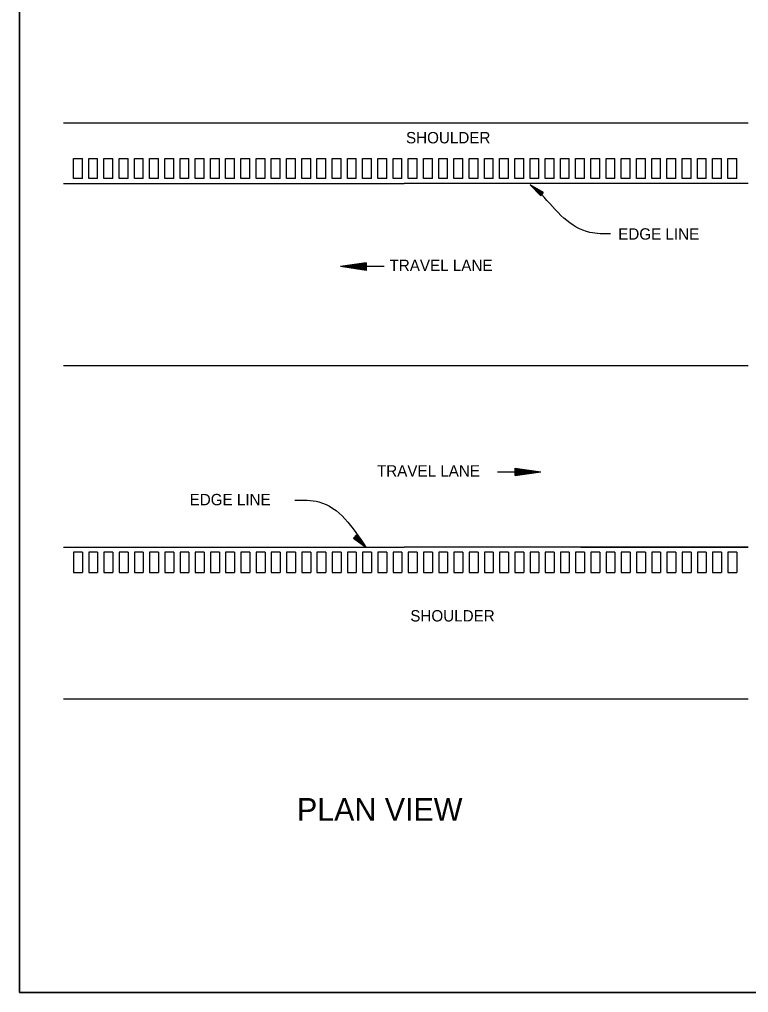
# Model space of a CAD drawing. Extents: x 8229 to 8749, y 14916 to 18021.
# Drawn here: x 8230.8 to 8356.5, y 15353.5 to 15521.2 of the extents above; entities that cross this region are included whole.
import ezdxf

# ---------------------------------------------------------------- set-up
doc = ezdxf.new("R2010")
doc.units = 0
doc.layers.add('Default', color=7, linetype='Continuous')
doc.layers.add('DSN_DRFT_Junk-No-Plot', color=7, linetype='Continuous')

msp = doc.modelspace()

# ---------------------------------------------------------------- linework, layer by layer
at = {"layer": 'Default'}
for p, q in [((8238.44, 15503.35), (8356.39, 15503.35)), ((8240.14, 15493.77), (8240.14, 15497.24)), ((8240.14, 15497.24), (8241.68, 15497.24)), ((8241.68, 15493.77), (8241.68, 15497.24)), ((8242.77, 15493.77), (8242.77, 15497.24)), ((8242.77, 15497.24), (8244.3, 15497.24)), ((8244.3, 15493.77), (8244.3, 15497.24)), ((8245.39, 15493.77), (8245.39, 15497.24)), ((8245.39, 15497.24), (8246.92, 15497.24)), ((8246.92, 15493.77), (8246.92, 15497.24)), ((8248.01, 15493.77), (8248.01, 15497.24)), ((8248.01, 15497.24), (8249.54, 15497.24)), ((8249.54, 15493.77), (8249.54, 15497.24)), ((8250.63, 15493.77), (8250.63, 15497.24)), ((8250.63, 15497.24), (8252.17, 15497.24)), ((8252.17, 15493.77), (8252.17, 15497.24)), ((8253.25, 15493.77), (8253.25, 15497.24)), ((8253.25, 15497.24), (8254.79, 15497.24)), ((8254.79, 15493.77), (8254.79, 15497.24)), ((8255.88, 15493.77), (8255.88, 15497.24)), ((8255.88, 15497.24), (8257.41, 15497.24)), ((8257.41, 15493.77), (8257.41, 15497.24)), ((8258.5, 15493.77), (8258.5, 15497.24)), ((8258.5, 15497.24), (8260.03, 15497.24)), ((8260.03, 15493.77), (8260.03, 15497.24)), ((8261.12, 15493.77), (8261.12, 15497.24)), ((8261.12, 15497.24), (8262.65, 15497.24)), ((8262.65, 15493.77), (8262.65, 15497.24)), ((8263.74, 15493.77), (8263.74, 15497.24)), ((8263.74, 15497.24), (8265.28, 15497.24)), ((8265.28, 15493.77), (8265.28, 15497.24)), ((8266.36, 15493.77), (8266.36, 15497.24)), ((8266.36, 15497.24), (8267.9, 15497.24)), ((8267.9, 15493.77), (8267.9, 15497.24)), ((8268.99, 15493.77), (8268.99, 15497.24)), ((8268.99, 15497.24), (8270.52, 15497.24)), ((8270.52, 15493.77), (8270.52, 15497.24)), ((8271.61, 15493.77), (8271.61, 15497.24)), ((8271.61, 15497.24), (8273.14, 15497.24)), ((8273.14, 15493.77), (8273.14, 15497.24)), ((8274.23, 15493.77), (8274.23, 15497.24)), ((8274.23, 15497.24), (8275.76, 15497.24)), ((8275.76, 15493.77), (8275.76, 15497.24)), ((8276.85, 15493.77), (8276.85, 15497.24)), ((8276.85, 15497.24), (8278.39, 15497.24)), ((8278.39, 15493.77), (8278.39, 15497.24)), ((8279.47, 15493.77), (8279.47, 15497.24)), ((8279.47, 15493.77), (8279.47, 15497.24)), ((8279.47, 15497.24), (8281.01, 15497.24)), ((8281.01, 15493.77), (8281.01, 15497.24)), ((8282.1, 15493.77), (8282.1, 15497.24)), ((8282.1, 15497.24), (8283.63, 15497.24)), ((8283.63, 15493.77), (8283.63, 15497.24)), ((8284.72, 15493.77), (8284.72, 15497.24)), ((8284.72, 15497.24), (8286.25, 15497.24)), ((8286.25, 15493.77), (8286.25, 15497.24)), ((8287.34, 15493.77), (8287.34, 15497.24)), ((8287.34, 15497.24), (8288.87, 15497.24)), ((8288.87, 15493.77), (8288.87, 15497.24)), ((8289.96, 15493.77), (8289.96, 15497.24)), ((8289.96, 15497.24), (8291.5, 15497.24)), ((8291.5, 15493.77), (8291.5, 15497.24)), ((8292.59, 15493.77), (8292.59, 15497.24)), ((8292.59, 15497.24), (8294.12, 15497.24)), ((8294.12, 15493.77), (8294.12, 15497.24)), ((8295.21, 15493.77), (8295.21, 15497.24)), ((8295.21, 15497.24), (8296.74, 15497.24)), ((8296.74, 15493.77), (8296.74, 15497.24)), ((8297.83, 15493.77), (8297.83, 15497.24)), ((8297.83, 15497.24), (8299.36, 15497.24)), ((8299.36, 15493.77), (8299.36, 15497.24)), ((8300.45, 15493.77), (8300.45, 15497.24)), ((8300.45, 15497.24), (8301.99, 15497.24)), ((8301.99, 15493.77), (8301.99, 15497.24)), ((8303.07, 15493.77), (8303.07, 15497.24)), ((8303.07, 15497.24), (8304.61, 15497.24)), ((8304.61, 15493.77), (8304.61, 15497.24)), ((8305.7, 15493.77), (8305.7, 15497.24)), ((8305.7, 15497.24), (8307.23, 15497.24)), ((8307.23, 15493.77), (8307.23, 15497.24)), ((8308.32, 15493.77), (8308.32, 15497.24)), ((8308.32, 15497.24), (8309.85, 15497.24)), ((8309.85, 15493.77), (8309.85, 15497.24)), ((8310.94, 15493.77), (8310.94, 15497.24)), ((8310.94, 15497.24), (8312.47, 15497.24)), ((8312.47, 15493.77), (8312.47, 15497.24)), ((8313.56, 15493.77), (8313.56, 15497.24)), ((8313.56, 15497.24), (8315.1, 15497.24)), ((8315.1, 15493.77), (8315.1, 15497.24)), ((8316.18, 15493.77), (8316.18, 15497.24)), ((8316.18, 15497.24), (8317.72, 15497.24)), ((8317.72, 15493.77), (8317.72, 15497.24)), ((8318.81, 15493.77), (8318.81, 15497.24)), ((8318.81, 15497.24), (8320.34, 15497.24)), ((8320.34, 15493.77), (8320.34, 15497.24)), ((8321.43, 15493.77), (8321.43, 15497.24)), ((8321.43, 15497.24), (8322.96, 15497.24)), ((8322.96, 15493.77), (8322.96, 15497.24)), ((8324.05, 15493.77), (8324.05, 15497.24)), ((8324.05, 15497.24), (8325.58, 15497.24)), ((8325.58, 15493.77), (8325.58, 15497.24)), ((8326.67, 15493.77), (8326.67, 15497.24)), ((8326.67, 15497.24), (8328.21, 15497.24)), ((8328.21, 15493.77), (8328.21, 15497.24)), ((8329.29, 15493.77), (8329.29, 15497.24)), ((8329.29, 15497.24), (8330.83, 15497.24)), ((8330.83, 15493.77), (8330.83, 15497.24)), ((8331.92, 15493.77), (8331.92, 15497.24)), ((8331.92, 15497.24), (8333.45, 15497.24)), ((8333.45, 15493.77), (8333.45, 15497.24)), ((8334.54, 15493.77), (8334.54, 15497.24)), ((8334.54, 15497.24), (8336.07, 15497.24)), ((8336.07, 15493.77), (8336.07, 15497.24)), ((8337.16, 15493.77), (8337.16, 15497.24)), ((8337.16, 15497.24), (8338.69, 15497.24)), ((8338.69, 15493.77), (8338.69, 15497.24)), ((8339.78, 15493.77), (8339.78, 15497.24)), ((8339.78, 15497.24), (8341.32, 15497.24)), ((8341.32, 15493.77), (8341.32, 15497.24)), ((8342.41, 15493.77), (8342.41, 15497.24)), ((8342.41, 15497.24), (8343.94, 15497.24)), ((8343.94, 15493.77), (8343.94, 15497.24)), ((8345.03, 15493.77), (8345.03, 15497.24)), ((8345.03, 15497.24), (8346.56, 15497.24)), ((8346.56, 15493.77), (8346.56, 15497.24)), ((8347.65, 15493.77), (8347.65, 15497.24)), ((8347.65, 15497.24), (8349.18, 15497.24)), ((8349.18, 15493.77), (8349.18, 15497.24)), ((8350.27, 15493.77), (8350.27, 15497.24)), ((8350.27, 15497.24), (8351.81, 15497.24)), ((8351.81, 15493.77), (8351.81, 15497.24)), ((8352.89, 15493.77), (8352.89, 15497.24)), ((8352.89, 15497.24), (8354.43, 15497.24)), ((8354.43, 15493.77), (8354.43, 15497.24)), ((8241.68, 15493.77), (8240.14, 15493.77)), ((8244.3, 15493.77), (8242.77, 15493.77)), ((8246.92, 15493.77), (8245.39, 15493.77)), ((8249.54, 15493.77), (8248.01, 15493.77)), ((8252.17, 15493.77), (8250.63, 15493.77)), ((8254.79, 15493.77), (8253.25, 15493.77)), ((8257.41, 15493.77), (8255.88, 15493.77)), ((8260.03, 15493.77), (8258.5, 15493.77)), ((8262.65, 15493.77), (8261.12, 15493.77)), ((8265.28, 15493.77), (8263.74, 15493.77)), ((8267.9, 15493.77), (8266.36, 15493.77)), ((8270.52, 15493.77), (8268.99, 15493.77)), ((8273.14, 15493.77), (8271.61, 15493.77)), ((8275.76, 15493.77), (8274.23, 15493.77)), ((8278.39, 15493.77), (8276.85, 15493.77)), ((8281.01, 15493.77), (8279.47, 15493.77)), ((8283.63, 15493.77), (8282.1, 15493.77)), ((8286.25, 15493.77), (8284.72, 15493.77)), ((8288.87, 15493.77), (8287.34, 15493.77)), ((8291.5, 15493.77), (8289.96, 15493.77)), ((8294.12, 15493.77), (8292.59, 15493.77)), ((8296.74, 15493.77), (8295.21, 15493.77)), ((8299.36, 15493.77), (8297.83, 15493.77)), ((8301.99, 15493.77), (8300.45, 15493.77)), ((8304.61, 15493.77), (8303.07, 15493.77)), ((8307.23, 15493.77), (8305.7, 15493.77)), ((8309.85, 15493.77), (8308.32, 15493.77)), ((8312.47, 15493.77), (8310.94, 15493.77)), ((8315.1, 15493.77), (8313.56, 15493.77)), ((8317.72, 15493.77), (8316.18, 15493.77)), ((8320.34, 15493.77), (8318.81, 15493.77)), ((8322.96, 15493.77), (8321.43, 15493.77)), ((8325.58, 15493.77), (8324.05, 15493.77)), ((8328.21, 15493.77), (8326.67, 15493.77)), ((8330.83, 15493.77), (8329.29, 15493.77)), ((8333.45, 15493.77), (8331.92, 15493.77)), ((8336.07, 15493.77), (8334.54, 15493.77)), ((8338.69, 15493.77), (8337.16, 15493.77)), ((8341.32, 15493.77), (8339.78, 15493.77)), ((8343.94, 15493.77), (8342.41, 15493.77)), ((8346.56, 15493.77), (8345.03, 15493.77)), ((8349.18, 15493.77), (8347.65, 15493.77)), ((8351.81, 15493.77), (8350.27, 15493.77)), ((8354.43, 15493.77), (8352.89, 15493.77)), ((8238.44, 15492.9), (8297.14, 15492.9)), ((8356.39, 15492.9), (8297.14, 15492.9)), ((8320.65, 15490.76), (8318.85, 15492.7)), ((8321.14, 15491.38), (8318.85, 15492.7)), ((8320.69, 15490.81), (8319.19, 15492.43)), ((8321.1, 15491.32), (8319.19, 15492.43)), ((8321.05, 15491.27), (8319.54, 15492.15)), ((8320.73, 15490.87), (8319.54, 15492.15)), ((8320.77, 15490.92), (8319.88, 15491.88)), ((8321.02, 15491.22), (8319.88, 15491.88)), ((8320.97, 15491.17), (8320.23, 15491.6)), ((8320.81, 15490.97), (8320.23, 15491.6)), ((8320.93, 15491.11), (8320.57, 15491.33)), ((8320.85, 15491.02), (8320.57, 15491.33)), ((8320.65, 15490.76), (8321.14, 15491.38)), ((8290.56, 15479.24), (8286.15, 15478.58)), ((8293.65, 15478.58), (8286.15, 15478.58)), ((8290.56, 15477.93), (8286.15, 15478.58)), ((8290.56, 15479.13), (8286.89, 15478.58)), ((8290.56, 15478.03), (8286.89, 15478.58)), ((8290.56, 15479.02), (8287.64, 15478.58)), ((8290.56, 15478.15), (8287.64, 15478.58)), ((8290.56, 15478.91), (8288.37, 15478.58)), ((8290.56, 15478.25), (8288.37, 15478.58)), ((8290.56, 15478.79), (8289.12, 15478.58)), ((8290.56, 15478.37), (8289.12, 15478.58)), ((8290.56, 15478.69), (8289.86, 15478.58)), ((8290.56, 15478.48), (8289.86, 15478.58)), ((8290.56, 15479.24), (8290.56, 15477.93)), ((8238.44, 15461.57), (8356.39, 15461.57)), ((8313.18, 15443.24), (8320.68, 15443.24)), ((8316.28, 15443.88), (8320.68, 15443.24)), ((8316.28, 15442.58), (8316.28, 15443.88)), ((8316.28, 15443.78), (8319.95, 15443.24)), ((8316.28, 15443.67), (8319.19, 15443.24)), ((8316.28, 15443.56), (8318.47, 15443.24)), ((8316.28, 15443.44), (8317.71, 15443.24)), ((8316.28, 15443.34), (8316.98, 15443.24)), ((8316.28, 15442.58), (8320.68, 15443.24)), ((8316.28, 15443.02), (8317.71, 15443.24)), ((8316.28, 15442.79), (8319.19, 15443.24)), ((8316.28, 15442.68), (8319.95, 15443.24)), ((8316.28, 15442.9), (8318.47, 15443.24)), ((8316.28, 15443.12), (8316.98, 15443.24)), ((8288.91, 15432.36), (8288.37, 15431.8)), ((8288.37, 15431.8), (8290.53, 15430.26)), ((8288.42, 15431.85), (8290.21, 15430.57)), ((8288.46, 15431.89), (8289.88, 15430.88)), ((8288.51, 15431.94), (8289.58, 15431.18)), ((8288.55, 15431.98), (8289.26, 15431.49)), ((8288.6, 15432.03), (8288.94, 15431.79)), ((8288.68, 15432.12), (8288.94, 15431.79)), ((8288.73, 15432.17), (8289.26, 15431.49)), ((8288.78, 15432.22), (8289.58, 15431.18)), ((8288.82, 15432.26), (8289.88, 15430.88)), ((8288.87, 15432.31), (8290.21, 15430.57)), ((8288.91, 15432.36), (8290.53, 15430.26)), ((8238.44, 15430.24), (8297.14, 15430.24)), ((8356.39, 15430.24), (8297.14, 15430.24)), ((8327.59, 15430.24), (8356.39, 15430.24)), ((8241.68, 15429.37), (8240.14, 15429.37)), ((8240.14, 15429.37), (8240.14, 15425.9)), ((8241.68, 15429.37), (8241.68, 15425.9)), ((8244.3, 15429.37), (8242.77, 15429.37)), ((8242.77, 15429.37), (8242.77, 15425.9)), ((8244.3, 15429.37), (8244.3, 15425.9)), ((8246.92, 15429.37), (8245.39, 15429.37)), ((8245.39, 15429.37), (8245.39, 15425.9)), ((8246.92, 15429.37), (8246.92, 15425.9)), ((8249.54, 15429.37), (8248.01, 15429.37)), ((8248.01, 15429.37), (8248.01, 15425.9)), ((8249.54, 15429.37), (8249.54, 15425.9)), ((8252.17, 15429.37), (8250.63, 15429.37)), ((8250.63, 15429.37), (8250.63, 15425.9)), ((8252.17, 15429.37), (8252.17, 15425.9)), ((8254.79, 15429.37), (8253.25, 15429.37)), ((8253.25, 15429.37), (8253.25, 15425.9)), ((8254.79, 15429.37), (8254.79, 15425.9)), ((8257.41, 15429.37), (8255.88, 15429.37)), ((8255.88, 15429.37), (8255.88, 15425.9)), ((8257.41, 15429.37), (8257.41, 15425.9)), ((8260.03, 15429.37), (8258.5, 15429.37)), ((8258.5, 15429.37), (8258.5, 15425.9)), ((8260.03, 15429.37), (8260.03, 15425.9)), ((8262.65, 15429.37), (8261.12, 15429.37)), ((8261.12, 15429.37), (8261.12, 15425.9)), ((8262.65, 15429.37), (8262.65, 15425.9)), ((8265.28, 15429.37), (8263.74, 15429.37)), ((8263.74, 15429.37), (8263.74, 15425.9)), ((8265.28, 15429.37), (8265.28, 15425.9)), ((8267.9, 15429.37), (8266.36, 15429.37)), ((8266.36, 15429.37), (8266.36, 15425.9)), ((8267.9, 15429.37), (8267.9, 15425.9)), ((8270.52, 15429.37), (8268.99, 15429.37)), ((8268.99, 15429.37), (8268.99, 15425.9)), ((8270.52, 15429.37), (8270.52, 15425.9)), ((8273.14, 15429.37), (8271.61, 15429.37)), ((8271.61, 15429.37), (8271.61, 15425.9)), ((8273.14, 15429.37), (8273.14, 15425.9)), ((8275.76, 15429.37), (8274.23, 15429.37)), ((8274.23, 15429.37), (8274.23, 15425.9)), ((8275.76, 15429.37), (8275.76, 15425.9)), ((8278.39, 15429.37), (8276.85, 15429.37)), ((8276.85, 15429.37), (8276.85, 15425.9)), ((8278.39, 15429.37), (8278.39, 15425.9)), ((8281.01, 15429.37), (8279.47, 15429.37)), ((8279.47, 15429.37), (8279.47, 15425.9)), ((8281.01, 15429.37), (8281.01, 15425.9)), ((8283.63, 15429.37), (8282.1, 15429.37)), ((8282.1, 15429.37), (8282.1, 15425.9)), ((8283.63, 15429.37), (8283.63, 15425.9)), ((8286.25, 15429.37), (8284.72, 15429.37)), ((8284.72, 15429.37), (8284.72, 15425.9)), ((8286.25, 15429.37), (8286.25, 15425.9)), ((8288.87, 15429.37), (8287.34, 15429.37)), ((8287.34, 15429.37), (8287.34, 15425.9)), ((8288.87, 15429.37), (8288.87, 15425.9)), ((8291.5, 15429.37), (8289.96, 15429.37)), ((8289.96, 15429.37), (8289.96, 15425.9)), ((8291.5, 15429.37), (8291.5, 15425.9)), ((8294.12, 15429.37), (8292.59, 15429.37)), ((8292.59, 15429.37), (8292.59, 15425.9)), ((8294.12, 15429.37), (8294.12, 15425.9)), ((8296.74, 15429.37), (8295.21, 15429.37)), ((8295.21, 15429.37), (8295.21, 15425.9)), ((8296.74, 15429.37), (8296.74, 15425.9)), ((8299.36, 15429.37), (8297.83, 15429.37)), ((8297.83, 15429.37), (8297.83, 15425.9)), ((8299.36, 15429.37), (8299.36, 15425.9)), ((8301.99, 15429.37), (8300.45, 15429.37)), ((8300.45, 15429.37), (8300.45, 15425.9)), ((8301.99, 15429.37), (8301.99, 15425.9)), ((8304.61, 15429.37), (8303.07, 15429.37)), ((8303.07, 15429.37), (8303.07, 15425.9)), ((8304.61, 15429.37), (8304.61, 15425.9)), ((8307.23, 15429.37), (8305.7, 15429.37)), ((8305.7, 15429.37), (8305.7, 15425.9)), ((8307.23, 15429.37), (8307.23, 15425.9)), ((8309.85, 15429.37), (8308.32, 15429.37)), ((8308.32, 15429.37), (8308.32, 15425.9)), ((8309.85, 15429.37), (8309.85, 15425.9)), ((8312.47, 15429.37), (8310.94, 15429.37)), ((8310.94, 15429.37), (8310.94, 15425.9)), ((8312.47, 15429.37), (8312.47, 15425.9)), ((8315.1, 15429.37), (8313.56, 15429.37)), ((8313.56, 15429.37), (8313.56, 15425.9)), ((8315.1, 15429.37), (8315.1, 15425.9)), ((8317.72, 15429.37), (8316.18, 15429.37)), ((8316.18, 15429.37), (8316.18, 15425.9)), ((8317.72, 15429.37), (8317.72, 15425.9)), ((8320.34, 15429.37), (8318.81, 15429.37)), ((8318.81, 15429.37), (8318.81, 15425.9)), ((8320.34, 15429.37), (8320.34, 15425.9)), ((8322.96, 15429.37), (8321.43, 15429.37)), ((8321.43, 15429.37), (8321.43, 15425.9)), ((8322.96, 15429.37), (8322.96, 15425.9)), ((8325.58, 15429.37), (8324.05, 15429.37)), ((8324.05, 15429.37), (8324.05, 15425.9)), ((8325.58, 15429.37), (8325.58, 15425.9)), ((8328.21, 15429.37), (8326.67, 15429.37)), ((8326.67, 15429.37), (8326.67, 15425.9)), ((8328.21, 15429.37), (8328.21, 15425.9)), ((8330.83, 15429.37), (8329.29, 15429.37)), ((8329.29, 15429.37), (8329.29, 15425.9)), ((8330.83, 15429.37), (8330.83, 15425.9)), ((8333.45, 15429.37), (8331.92, 15429.37)), ((8331.92, 15429.37), (8331.92, 15425.9)), ((8333.45, 15429.37), (8333.45, 15425.9)), ((8336.07, 15429.37), (8334.54, 15429.37)), ((8334.54, 15429.37), (8334.54, 15425.9)), ((8336.07, 15429.37), (8336.07, 15425.9)), ((8338.69, 15429.37), (8337.16, 15429.37)), ((8337.16, 15429.37), (8337.16, 15425.9)), ((8338.69, 15429.37), (8338.69, 15425.9)), ((8341.32, 15429.37), (8339.78, 15429.37)), ((8339.78, 15429.37), (8339.78, 15425.9)), ((8341.32, 15429.37), (8341.32, 15425.9)), ((8343.94, 15429.37), (8342.41, 15429.37)), ((8342.41, 15429.37), (8342.41, 15425.9)), ((8343.94, 15429.37), (8343.94, 15425.9)), ((8346.56, 15429.37), (8345.03, 15429.37)), ((8345.03, 15429.37), (8345.03, 15425.9)), ((8346.56, 15429.37), (8346.56, 15425.9)), ((8349.18, 15429.37), (8347.65, 15429.37)), ((8347.65, 15429.37), (8347.65, 15425.9)), ((8349.18, 15429.37), (8349.18, 15425.9)), ((8351.81, 15429.37), (8350.27, 15429.37)), ((8350.27, 15429.37), (8350.27, 15425.9)), ((8351.81, 15429.37), (8351.81, 15425.9)), ((8354.43, 15429.37), (8352.89, 15429.37)), ((8352.89, 15429.37), (8352.89, 15425.9)), ((8354.43, 15429.37), (8354.43, 15425.9)), ((8240.14, 15425.9), (8241.68, 15425.9)), ((8242.77, 15425.9), (8244.3, 15425.9)), ((8245.39, 15425.9), (8246.92, 15425.9)), ((8248.01, 15425.9), (8249.54, 15425.9)), ((8250.63, 15425.9), (8252.17, 15425.9)), ((8253.25, 15425.9), (8254.79, 15425.9)), ((8255.88, 15425.9), (8257.41, 15425.9)), ((8258.5, 15425.9), (8260.03, 15425.9)), ((8261.12, 15425.9), (8262.65, 15425.9)), ((8263.74, 15425.9), (8265.28, 15425.9)), ((8266.36, 15425.9), (8267.9, 15425.9)), ((8268.99, 15425.9), (8270.52, 15425.9)), ((8271.61, 15425.9), (8273.14, 15425.9)), ((8274.23, 15425.9), (8275.76, 15425.9)), ((8276.85, 15425.9), (8278.39, 15425.9)), ((8279.47, 15425.9), (8281.01, 15425.9)), ((8282.1, 15425.9), (8283.63, 15425.9)), ((8284.72, 15425.9), (8286.25, 15425.9)), ((8287.34, 15425.9), (8288.87, 15425.9)), ((8289.96, 15425.9), (8291.5, 15425.9)), ((8292.59, 15425.9), (8294.12, 15425.9)), ((8295.21, 15425.9), (8296.74, 15425.9)), ((8297.83, 15425.9), (8299.36, 15425.9)), ((8300.45, 15425.9), (8301.99, 15425.9)), ((8303.07, 15425.9), (8304.61, 15425.9)), ((8305.7, 15425.9), (8307.23, 15425.9)), ((8308.32, 15425.9), (8309.85, 15425.9)), ((8310.94, 15425.9), (8312.47, 15425.9)), ((8313.56, 15425.9), (8315.1, 15425.9)), ((8316.18, 15425.9), (8317.72, 15425.9)), ((8318.81, 15425.9), (8320.34, 15425.9)), ((8321.43, 15425.9), (8322.96, 15425.9)), ((8324.05, 15425.9), (8325.58, 15425.9)), ((8326.67, 15425.9), (8328.21, 15425.9)), ((8329.29, 15425.9), (8330.83, 15425.9)), ((8331.92, 15425.9), (8333.45, 15425.9)), ((8334.54, 15425.9), (8336.07, 15425.9)), ((8337.16, 15425.9), (8338.69, 15425.9)), ((8339.78, 15425.9), (8341.32, 15425.9)), ((8342.41, 15425.9), (8343.94, 15425.9)), ((8345.03, 15425.9), (8346.56, 15425.9)), ((8347.65, 15425.9), (8349.18, 15425.9)), ((8350.27, 15425.9), (8351.81, 15425.9)), ((8352.89, 15425.9), (8354.43, 15425.9)), ((8238.44, 15404.13), (8356.39, 15404.13))]:
    msp.add_line(p, q, dxfattribs=at)
msp.add_lwpolyline([(8748.98, 15353.52), (8748.98, 15688.81), (8230.82, 15688.81), (8230.82, 15353.52)], close=True, dxfattribs=at)
for points in [[(8332.7, 15484.21), (8329.15, 15484.47), (8320.8, 15491.09)], [(8278.27, 15438.34), (8282.44, 15438.05), (8290.53, 15430.26)]]:
    msp.add_spline(points, degree=3, dxfattribs=at)
at = {"layer": 'DSN_DRFT_Junk-No-Plot'}
msp.add_lwpolyline([(8230.82, 15688.81), (8748.98, 15688.81), (8748.98, 15353.52), (8230.82, 15353.52)], close=True, dxfattribs=at)

# ---------------------------------------------------------------- texts
at = {"layer": 'Default'}
for s, height, p in [('SHOULDER', 1.958, (8297.44, 15499.82)), ('EDGE LINE', 1.958, (8334.01, 15483.23)), ('TRAVEL LANE', 1.9582, (8294.6, 15477.82)), ('TRAVEL LANE', 1.9582, (8292.43, 15442.42)), ('EDGE LINE', 1.958, (8260.15, 15437.47)), ('SHOULDER', 1.958, (8298.18, 15417.45)), ('PLAN VIEW ', 3.916, (8278.65, 15383.11))]:
    msp.add_text(s, height=height, dxfattribs=at).set_placement(p)

doc.saveas('drawing.dxf')
